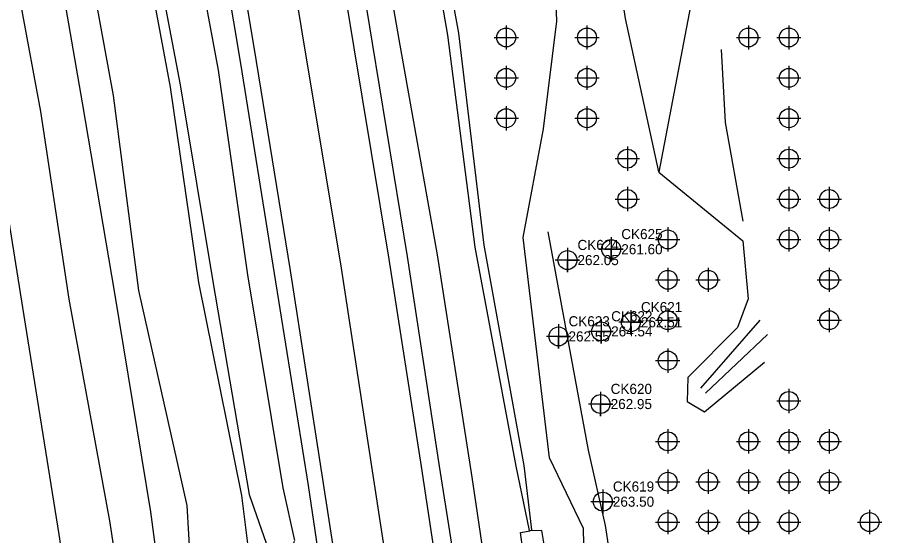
# Model space of a CAD drawing. Extents: x 1941547 to 1942851, y 663002 to 668358.
# Drawn here: x 1942528.9 to 1942743, y 663766.6 to 663895 of the extents above; entities that cross this region are included whole.
import ezdxf

# ---------------------------------------------------------------- set-up
doc = ezdxf.new("R2010")
doc.units = 0
for name, color, linetype in [('CTL GPS Vertical Cogo Elevation', 7, 'Continuous'), ('CTL NGS Vertical CELL', 7, 'Continuous'), ('Exist DTM Drainline Cogo Elevation', 7, 'Continuous'), ('Exist DTM QL2 LIDAR Elevation Point', 7, 'Continuous'), ('Exist Property Iron Pin Cogo Number', 7, 'Continuous'), ('Exist Roads EOP Cogo Point CELL', 7, 'Continuous'), ('Exist Roads EOT', 7, 'Continuous'), ('Exist Structure Minor Paved Ditch or Gutter', 7, 'Continuous'), ('Exist Utilities Telephone UG Cable SUE LOS C Cogo Elevation', 7, 'Continuous'), ('Exist Utilities Telephone UG FO SUE LOS C Cogo Elevation', 7, 'Continuous')]:
    doc.layers.add(name, color=color, linetype=linetype)

msp = doc.modelspace()

# ---------------------------------------------------------------- linework, layer by layer
at = {"layer": 'CTL NGS Vertical CELL'}
for p, q in [((1942698.17, 663803.16), (1942712.88, 663820.04)), ((1942699.32, 663801.95), (1942714.75, 663816.44))]:
    msp.add_line(p, q, dxfattribs=at)
for points in [[(1942655.72, 663767.91), (1942652.45, 663783.83), (1942642.31, 663838.1), (1942635.54, 663890.54), (1942626.29, 663943.71), (1942618.26, 663993.63), (1942609.63, 664042.29), (1942600.22, 664095.31), (1942589.46, 664147.55), (1942579.52, 664198.33), (1942571.22, 664237.31)], [(1942656.36, 663768.1), (1942654.42, 663784.04), (1942644.57, 663838.6), (1942638.24, 663891.08), (1942628.63, 663943.96), (1942621.59, 663994.45), (1942611.64, 664042.87), (1942602.45, 664095.81), (1942591.46, 664147.75), (1942582.85, 664198.84), (1942573.64, 664237.77)], [(1942655.72, 663767.91), (1942652.45, 663783.83), (1942642.31, 663838.1), (1942635.54, 663890.54), (1942626.29, 663943.71), (1942618.26, 663993.63), (1942609.63, 664042.29), (1942600.22, 664095.31), (1942589.46, 664147.55), (1942579.52, 664198.33)], [(1942656.36, 663768.1), (1942654.42, 663784.04), (1942644.57, 663838.6), (1942638.24, 663891.08), (1942628.63, 663943.96), (1942621.59, 663994.45), (1942611.64, 664042.87), (1942602.45, 664095.81), (1942591.46, 664147.75), (1942582.85, 664198.84)], [(1942547.16, 664000.42), (1942551.52, 663980.48), (1942559.12, 663931.27), (1942569.26, 663878.29), (1942577.32, 663829.55), (1942586.36, 663776.82), (1942591.07, 663763.12)], [(1942544.9, 663999.72), (1942549.05, 663980.05), (1942556.84, 663930.93), (1942566.74, 663877.7), (1942573.77, 663829.36), (1942584.43, 663776.55), (1942586.26, 663762.03)]]:
    msp.add_lwpolyline(points, dxfattribs=at)
at = {"layer": 'Exist DTM Drainline Cogo Elevation'}
for points in [[(1942676, 663840.57), (1942676, 663834.57), (1942676, 663837.57), (1942679, 663837.57), (1942673, 663837.57)], [(1942676, 663840.57), (1942676, 663834.57), (1942676, 663837.57), (1942679, 663837.57), (1942673, 663837.57)], [(1942665.15, 663837.88), (1942665.15, 663831.88), (1942665.15, 663834.88), (1942668.15, 663834.88), (1942662.15, 663834.88)], [(1942665.15, 663837.88), (1942665.15, 663831.88), (1942665.15, 663834.88), (1942668.15, 663834.88), (1942662.15, 663834.88)], [(1942680.87, 663822.49), (1942680.87, 663816.49), (1942680.87, 663819.49), (1942683.87, 663819.49), (1942677.87, 663819.49)], [(1942680.87, 663822.49), (1942680.87, 663816.49), (1942680.87, 663819.49), (1942683.87, 663819.49), (1942677.87, 663819.49)], [(1942662.93, 663818.98), (1942662.93, 663812.98), (1942662.93, 663815.98), (1942665.93, 663815.98), (1942659.93, 663815.98)], [(1942662.93, 663818.98), (1942662.93, 663812.98), (1942662.93, 663815.98), (1942665.93, 663815.98), (1942659.93, 663815.98)], [(1942673.49, 663820.23), (1942673.49, 663814.23), (1942673.49, 663817.23), (1942676.49, 663817.23), (1942670.49, 663817.23)], [(1942673.49, 663820.23), (1942673.49, 663814.23), (1942673.49, 663817.23), (1942676.49, 663817.23), (1942670.49, 663817.23)], [(1942673.37, 663802.24), (1942673.37, 663796.24), (1942673.37, 663799.24), (1942676.37, 663799.24), (1942670.37, 663799.24)], [(1942673.37, 663802.24), (1942673.37, 663796.24), (1942673.37, 663799.24), (1942676.37, 663799.24), (1942670.37, 663799.24)], [(1942673.91, 663778.06), (1942673.91, 663772.06), (1942673.91, 663775.06), (1942676.91, 663775.06), (1942670.91, 663775.06)], [(1942673.91, 663778.06), (1942673.91, 663772.06), (1942673.91, 663775.06), (1942676.91, 663775.06), (1942670.91, 663775.06)]]:
    msp.add_lwpolyline(points, dxfattribs=at)
for centre in [(1942676, 663837.57), (1942676, 663837.57), (1942665.15, 663834.88), (1942665.15, 663834.88), (1942680.87, 663819.49), (1942680.87, 663819.49), (1942662.93, 663815.98), (1942662.93, 663815.98), (1942673.49, 663817.23), (1942673.49, 663817.23), (1942673.37, 663799.24), (1942673.37, 663799.24), (1942673.91, 663775.06), (1942673.91, 663775.06)]:
    msp.add_circle(centre, 2.34, dxfattribs=at)
at = {"layer": 'Exist DTM QL2 LIDAR Elevation Point'}
for points in [[(1942650, 663893), (1942650, 663890)], [(1942670, 663893), (1942670, 663890)], [(1942710, 663893), (1942710, 663890)], [(1942720, 663893), (1942720, 663890)], [(1942647, 663890), (1942650, 663890)], [(1942650, 663890), (1942653, 663890)], [(1942650, 663890), (1942650, 663887)], [(1942667, 663890), (1942670, 663890)], [(1942670, 663890), (1942673, 663890)], [(1942670, 663890), (1942670, 663887)], [(1942707, 663890), (1942710, 663890)], [(1942710, 663890), (1942713, 663890)], [(1942710, 663890), (1942710, 663887)], [(1942717, 663890), (1942720, 663890)], [(1942720, 663890), (1942723, 663890)], [(1942720, 663890), (1942720, 663887)], [(1942650, 663883), (1942650, 663880)], [(1942670, 663883), (1942670, 663880)], [(1942720, 663883), (1942720, 663880)], [(1942647, 663880), (1942650, 663880)], [(1942650, 663880), (1942653, 663880)], [(1942650, 663880), (1942650, 663877)], [(1942667, 663880), (1942670, 663880)], [(1942670, 663880), (1942673, 663880)], [(1942670, 663880), (1942670, 663877)], [(1942717, 663880), (1942720, 663880)], [(1942720, 663880), (1942723, 663880)], [(1942720, 663880), (1942720, 663877)], [(1942650, 663873), (1942650, 663870)], [(1942670, 663873), (1942670, 663870)], [(1942720, 663873), (1942720, 663870)], [(1942647, 663870), (1942650, 663870)], [(1942650, 663870), (1942653, 663870)], [(1942650, 663870), (1942650, 663867)], [(1942667, 663870), (1942670, 663870)], [(1942670, 663870), (1942673, 663870)], [(1942670, 663870), (1942670, 663867)], [(1942717, 663870), (1942720, 663870)], [(1942720, 663870), (1942723, 663870)], [(1942720, 663870), (1942720, 663867)], [(1942680, 663863), (1942680, 663860)], [(1942720, 663863), (1942720, 663860)], [(1942677, 663860), (1942680, 663860)], [(1942680, 663860), (1942683, 663860)], [(1942680, 663860), (1942680, 663857)], [(1942717, 663860), (1942720, 663860)], [(1942720, 663860), (1942723, 663860)], [(1942720, 663860), (1942720, 663857)], [(1942680, 663853), (1942680, 663850)], [(1942720, 663853), (1942720, 663850)], [(1942730, 663853), (1942730, 663850)], [(1942677, 663850), (1942680, 663850)], [(1942680, 663850), (1942683, 663850)], [(1942680, 663850), (1942680, 663847)], [(1942717, 663850), (1942720, 663850)], [(1942720, 663850), (1942723, 663850)], [(1942720, 663850), (1942720, 663847)], [(1942727, 663850), (1942730, 663850)], [(1942730, 663850), (1942733, 663850)], [(1942730, 663850), (1942730, 663847)], [(1942690, 663843), (1942690, 663840)], [(1942720, 663843), (1942720, 663840)], [(1942730, 663843), (1942730, 663840)], [(1942687, 663840), (1942690, 663840)], [(1942690, 663840), (1942693, 663840)], [(1942690, 663840), (1942690, 663837)], [(1942717, 663840), (1942720, 663840)], [(1942720, 663840), (1942723, 663840)], [(1942720, 663840), (1942720, 663837)], [(1942727, 663840), (1942730, 663840)], [(1942730, 663840), (1942733, 663840)], [(1942730, 663840), (1942730, 663837)], [(1942690, 663833), (1942690, 663830)], [(1942700, 663833), (1942700, 663830)], [(1942730, 663833), (1942730, 663830)], [(1942687, 663830), (1942690, 663830)], [(1942690, 663830), (1942693, 663830)], [(1942690, 663830), (1942690, 663827)], [(1942697, 663830), (1942700, 663830)], [(1942700, 663830), (1942703, 663830)], [(1942700, 663830), (1942700, 663827)], [(1942727, 663830), (1942730, 663830)], [(1942730, 663830), (1942733, 663830)], [(1942730, 663830), (1942730, 663827)], [(1942690, 663823), (1942690, 663820)], [(1942730, 663823), (1942730, 663820)], [(1942687, 663820), (1942690, 663820)], [(1942690, 663820), (1942693, 663820)], [(1942690, 663820), (1942690, 663817)], [(1942727, 663820), (1942730, 663820)], [(1942730, 663820), (1942733, 663820)], [(1942730, 663820), (1942730, 663817)], [(1942690, 663813), (1942690, 663810)], [(1942687, 663810), (1942690, 663810)], [(1942690, 663810), (1942693, 663810)], [(1942690, 663810), (1942690, 663807)], [(1942720, 663803), (1942720, 663800)], [(1942717, 663800), (1942720, 663800)], [(1942720, 663800), (1942723, 663800)], [(1942720, 663800), (1942720, 663797)], [(1942690, 663793), (1942690, 663790)], [(1942710, 663793), (1942710, 663790)], [(1942720, 663793), (1942720, 663790)], [(1942730, 663793), (1942730, 663790)], [(1942687, 663790), (1942690, 663790)], [(1942690, 663790), (1942693, 663790)], [(1942690, 663790), (1942690, 663787)], [(1942707, 663790), (1942710, 663790)], [(1942710, 663790), (1942713, 663790)], [(1942710, 663790), (1942710, 663787)], [(1942717, 663790), (1942720, 663790)], [(1942720, 663790), (1942723, 663790)], [(1942720, 663790), (1942720, 663787)], [(1942727, 663790), (1942730, 663790)], [(1942730, 663790), (1942733, 663790)], [(1942730, 663790), (1942730, 663787)], [(1942690, 663783), (1942690, 663780)], [(1942700, 663783), (1942700, 663780)], [(1942710, 663783), (1942710, 663780)], [(1942720, 663783), (1942720, 663780)], [(1942730, 663783), (1942730, 663780)], [(1942687, 663780), (1942690, 663780)], [(1942690, 663780), (1942693, 663780)], [(1942690, 663780), (1942690, 663777)], [(1942697, 663780), (1942700, 663780)], [(1942700, 663780), (1942703, 663780)], [(1942700, 663780), (1942700, 663777)], [(1942707, 663780), (1942710, 663780)], [(1942710, 663780), (1942713, 663780)], [(1942710, 663780), (1942710, 663777)], [(1942717, 663780), (1942720, 663780)], [(1942720, 663780), (1942723, 663780)], [(1942720, 663780), (1942720, 663777)], [(1942727, 663780), (1942730, 663780)], [(1942730, 663780), (1942733, 663780)], [(1942730, 663780), (1942730, 663777)], [(1942690, 663773), (1942690, 663770)], [(1942700, 663773), (1942700, 663770)], [(1942710, 663773), (1942710, 663770)], [(1942720, 663773), (1942720, 663770)], [(1942740, 663773), (1942740, 663770)], [(1942687, 663770), (1942690, 663770)], [(1942690, 663770), (1942693, 663770)], [(1942690, 663770), (1942690, 663767)], [(1942697, 663770), (1942700, 663770)], [(1942700, 663770), (1942703, 663770)], [(1942700, 663770), (1942700, 663767)], [(1942707, 663770), (1942710, 663770)], [(1942710, 663770), (1942713, 663770)], [(1942710, 663770), (1942710, 663767)], [(1942717, 663770), (1942720, 663770)], [(1942720, 663770), (1942723, 663770)], [(1942720, 663770), (1942720, 663767)], [(1942737, 663770), (1942740, 663770)], [(1942740, 663770), (1942743, 663770)], [(1942740, 663770), (1942740, 663767)]]:
    msp.add_lwpolyline(points, dxfattribs=at)
for centre in [(1942650, 663890), (1942670, 663890), (1942710, 663890), (1942720, 663890), (1942650, 663880), (1942670, 663880), (1942720, 663880), (1942650, 663870), (1942670, 663870), (1942720, 663870), (1942680, 663860), (1942720, 663860), (1942680, 663850), (1942720, 663850), (1942730, 663850), (1942690, 663840), (1942720, 663840), (1942730, 663840), (1942690, 663830), (1942700, 663830), (1942730, 663830), (1942690, 663820), (1942730, 663820), (1942690, 663810), (1942720, 663800), (1942690, 663790), (1942710, 663790), (1942720, 663790), (1942730, 663790), (1942690, 663780), (1942700, 663780), (1942710, 663780), (1942720, 663780), (1942730, 663780), (1942690, 663770), (1942700, 663770), (1942710, 663770), (1942720, 663770), (1942740, 663770)]:
    msp.add_circle(centre, 2.34, dxfattribs=at)
at = {"layer": 'Exist Property Iron Pin Cogo Number'}
for points in [[(1942535.15, 664241.51), (1942545.15, 664190.98), (1942554.98, 664140.31), (1942564.32, 664090.5), (1942574.04, 664037.16), (1942583.23, 663987.29), (1942591.6, 663938.59), (1942600.26, 663885.84), (1942608.93, 663833.98), (1942616.95, 663781.65), (1942624.84, 663729.94), (1942632.77, 663678.03), (1942640.07, 663627.4), (1942648.8, 663569.13)], [(1942469.11, 664229.51), (1942479.32, 664178.41), (1942488.44, 664126.2), (1942498.23, 664078.36), (1942507.35, 664025.89), (1942516.11, 663975.05), (1942524.9, 663924.28), (1942534.61, 663871.67), (1942541.65, 663825.2), (1942551.69, 663770.28), (1942559.44, 663720.11), (1942567.31, 663666.58), (1942574.37, 663616.01)]]:
    msp.add_lwpolyline(points, dxfattribs=at)
at = {"layer": 'Exist Roads EOT'}
for points in [[(1942546.97, 664243.63), (1942556.97, 664193.32), (1942566.94, 664142.09), (1942576.07, 664092.72), (1942586.16, 664038.02), (1942595.11, 663989.06), (1942603.48, 663940.87), (1942612.18, 663887.97), (1942620.88, 663835.09), (1942628.9, 663783.73), (1942636.85, 663731.29), (1942644.5, 663679.83), (1942652.2, 663628.27), (1942660.61, 663571.1)], [(1942523.17, 664239.12), (1942533.04, 664188.65), (1942542.62, 664138), (1942551.99, 664088.35), (1942561.77, 664035.44), (1942570.75, 663985.57), (1942579.41, 663936.3), (1942588.02, 663884.03), (1942596.44, 663832.32), (1942604.62, 663779.52), (1942612.54, 663728.28), (1942620.39, 663676.29), (1942627.85, 663625.44), (1942636.28, 663567.77)]]:
    msp.add_lwpolyline(points, dxfattribs=at)
at = {"layer": 'Exist Structure Minor Paved Ditch or Gutter'}
for points in [[(1942658.92, 663746.56), (1942656.39, 663746.17), (1942653.53, 663767.46), (1942655.94, 663767.8)], [(1942659.52, 663746.66), (1942662.27, 663747.11), (1942658.78, 663767.89), (1942655.94, 663767.8)]]:
    msp.add_lwpolyline(points, dxfattribs=at)
at = {"layer": 'Exist Utilities Telephone UG Cable SUE LOS C Cogo Elevation'}
for points in [[(1942551.4, 664244.16), (1942561.16, 664194.29), (1942571.17, 664142.93), (1942580.34, 664093.62), (1942590.26, 664039.1), (1942599.47, 663989.58), (1942608.09, 663941.73), (1942616.79, 663888.57), (1942625.47, 663835.77), (1942633.35, 663783.87), (1942641.57, 663732.16), (1942649.42, 663680.73), (1942656.69, 663628.65), (1942664.5, 663571.56), (1942664.5, 663571.37)], [(1942519.27, 664238.37), (1942529.36, 664187.16), (1942538.68, 664137.83), (1942547.98, 664087.82), (1942558.12, 664035.31), (1942567.04, 663985.08), (1942575.41, 663935.76), (1942584.18, 663883.52), (1942592.48, 663831.55), (1942600.94, 663779.06), (1942608.52, 663727.77), (1942616.84, 663675.94), (1942624.37, 663625.04), (1942633.06, 663567.35)], [(1942480.15, 664231.77), (1942490.39, 664180.38), (1942499.92, 664128.29), (1942508.91, 664080.53), (1942518, 664027.54), (1942526.91, 663976.64), (1942535.93, 663925.89), (1942544.93, 663873.84), (1942552.98, 663826.65), (1942561.89, 663772.56), (1942568.71, 663720.88), (1942578.1, 663669.07), (1942585.79, 663617.73)], [(1942457.84, 664226.53), (1942467.5, 664175.95), (1942477.02, 664123.89), (1942486.19, 664076.28), (1942495.25, 664026.24), (1942504.3, 663972.93), (1942514.32, 663919.34), (1942522.78, 663869.39), (1942530.16, 663823.1), (1942539.21, 663766.97), (1942546.24, 663720.05), (1942555.51, 663665.17), (1942562.81, 663614.06)]]:
    msp.add_lwpolyline(points, dxfattribs=at)
at = {"layer": 'Exist Utilities Telephone UG FO SUE LOS C Cogo Elevation'}
for points in [[(1942698.67, 663570.27), (1942690.05, 663615.32), (1942687.8, 663633.74), (1942681.77, 663680.9), (1942669.81, 663737.7), (1942669.16, 663768.43), (1942660.74, 663785.94), (1942654.22, 663840.51), (1942659.2, 663867.37), (1942662.57, 663894.02), (1942660.53, 663948.94), (1942653.89, 663997.65), (1942646.16, 664051.26), (1942643.52, 664103.09), (1942633.42, 664153.43), (1942621.98, 664209.98), (1942611.29, 664238.27), (1942628.17, 664250.61)], [(1942513.96, 664238.19), (1942524.27, 664186.71), (1942533.64, 664135.36), (1942542.16, 664086.78), (1942550.96, 664032.56), (1942563, 663983.5), (1942569.17, 663932.97), (1942578.67, 663881.94), (1942585.89, 663831.2), (1942594.7, 663778.46), (1942597.56, 663765.43)], [(1942667.2, 663611.44), (1942663.75, 663629.46), (1942656.66, 663680.59), (1942647.81, 663732.78), (1942644.32, 663762.75), (1942641.56, 663781.09), (1942633.01, 663836.17), (1942623.47, 663889.48), (1942614.38, 663941.8), (1942605.73, 663991.44), (1942595.41, 664040.38), (1942587.5, 664094.08), (1942579.23, 664144.8), (1942568.86, 664196.24), (1942564.72, 664235.72)], [(1942486.28, 664231.91), (1942498.25, 664181.82), (1942504.65, 664129.09), (1942516.06, 664081.78), (1942525.22, 664029.73), (1942536.89, 663978.25), (1942543.16, 663927.53), (1942552.61, 663875.65), (1942558.95, 663827.39), (1942570.92, 663774.11), (1942571.72, 663759.9), (1942577.5, 663753.96), (1942586.38, 663751.95), (1942594.53, 663757.2), (1942597.54, 663765.29)], [(1942667.2, 663611.44), (1942663.75, 663629.46), (1942656.66, 663680.59), (1942647.81, 663732.78), (1942644.32, 663762.75), (1942641.56, 663781.09), (1942633.01, 663836.17), (1942623.47, 663889.48), (1942614.38, 663941.8), (1942605.73, 663991.44), (1942595.41, 664040.38), (1942587.5, 664094.08), (1942579.23, 664144.8), (1942568.86, 664196.24)], [(1942663.93, 663992.86), (1942671.51, 663946.51), (1942679.45, 663894.68), (1942687.7, 663856.75)], [(1942692.17, 663936.76), (1942695.97, 663899.53), (1942687.83, 663856.69), (1942708.63, 663839.68), (1942709.9, 663825.31), (1942707.26, 663818.19), (1942694.96, 663805.8), (1942694.85, 663799.9), (1942699.07, 663797.29), (1942713.96, 663809.62)], [(1942708.67, 663844.54), (1942704.33, 663868.96), (1942703.3, 663887.06)], [(1942704.84, 663616.1), (1942698.88, 663635.66), (1942692.14, 663682.12), (1942679.09, 663739.47), (1942674.62, 663769.17), (1942670.34, 663787.84), (1942660.41, 663841.9)]]:
    msp.add_lwpolyline(points, dxfattribs=at)

# ---------------------------------------------------------------- texts
at = {"layer": 'CTL GPS Vertical Cogo Elevation'}
for s, p in [('CK625', (1942678.5, 663840.07)), ('CK624', (1942667.65, 663837.38)), ('CK621', (1942683.37, 663821.99)), ('CK623', (1942665.43, 663818.48)), ('CK622', (1942675.99, 663819.73)), ('CK620', (1942675.87, 663801.74)), ('CK619', (1942676.41, 663777.56))]:
    msp.add_text(s, height=2.5, dxfattribs=at).set_placement(p)
at = {"layer": 'Exist Roads EOP Cogo Point CELL'}
for s, p in [('261.60', (1942678.5, 663836.32)), ('262.05', (1942667.65, 663833.63)), ('262.51', (1942683.37, 663818.24)), ('264.54', (1942675.99, 663815.98)), ('262.55', (1942665.43, 663814.73)), ('262.95', (1942675.87, 663797.99)), ('263.50', (1942676.41, 663773.81))]:
    msp.add_text(s, height=2.5, dxfattribs=at).set_placement(p)

doc.saveas('drawing.dxf')
